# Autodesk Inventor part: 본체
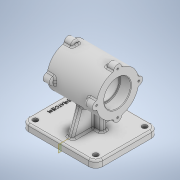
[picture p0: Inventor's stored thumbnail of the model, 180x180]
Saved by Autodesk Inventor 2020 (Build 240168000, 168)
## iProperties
Created: 2022-11
Part Number: 본체
Material: 일반
Document SubType Name: Modeling
Designer: owner
Density: 1 g/cm^3
Appearance: 기본값
Mass: 450.145 g
Surface Area: 796.917 cm^2
Volume: 450.145 cm^3
Author: owner
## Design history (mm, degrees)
sketch "스케치1"
  geometry: L1 (65, 55)-(-65, 55); L2 (-65, 55)-(-65, -55); L3 (-65, -55)-(65, -55); L4 (65, -55)-(65, 55); L5 (65, 55)-(-65, -55); L6 (-65, 55)-(65, -55); 1 further point
  constraints: 12 end point, 2 midpoint, 2 parallel, 1 horizontal, 1 perpendicular
  dimensions: "d0" = 130 distance of L3.end L2.end; "d1" = 110 distance of L2.end L1.end
extrude "돌출1" new body sketch "스케치1" distance "d2" = 12; taper "d3" = 0 deg
node "작업 평면1"
sketch "스케치2"
  geometry: L1 (0, 0)-(110, 0) reference; C1 r 37 at (55, 82); 2 further points
  constraints: 1 centre point, 1 midpoint, 1 vertical alignment
  dimensions: "d5" = 74 diameter of C1; "d6" = 82 distance from line of L1 C1.centre
extrude "돌출2" join sketch "스케치2" stored distance "d7" = 87; taper "d8" = 0 deg
sketch "스케치3"
  geometry: C1 r 37 at (0, 0) reference; 2 further points
  constraints: 1 coincident
hole "구멍1" sketch "스케치3" at (0, 0) diameter "d9" = 42; stored, may be unused: countersink angle "d13" = 90 deg, drill point angle "d15" = 0 deg; dims "d10" = 8, "d11" = 47, "d12" = 19, "d14" = 10
sketch "스케치4"
  geometry: C1 r 37 at (0, 0) reference; 2 further points
  constraints: 1 coincident
hole "구멍2" sketch "스케치4" at (0, 0) diameter "d16" = 42; stored, may be unused: countersink angle "d20" = 90 deg, drill point angle "d22" = 0 deg; dims "d17" = 8, "d18" = 47, "d19" = 19, "d21" = 10
sketch "스케치5"
  geometry: L1 (110, 0)-(0, 0) reference; L2 (0, 0)-(0, 12) reference; L3 (110, 12)-(0, 12) reference; L4 (110, 0)-(110, 12) reference; L5 (110, 12)-(0, 12) reference; L6 (96, 12)-(80.336, 55.036); L7 (14, 12)-(29.664, 55.036); C1 r 23.5 at (55, 82) reference; A1 r 37 centre (55, 82) between (80.336, 55.036) and (29.664, 55.036) reference; 3 further points
  constraints: 4 end point, 2 point on circle, 2 point on line
  dimensions: "d23" = 14 distance from line of L4 L6.start; "d24" = 14 distance from line of L2 L7.start; "d25" = 110 deg angle of L3 L6; "d26" = 110 deg angle of L3 L7
extrude "돌출3" join sketch "스케치5" stored distance "d27" = 10; taper "d28" = 0 deg
sketch "스케치6"
  geometry: L1 (-65, 12)-(65, 12) reference; L2 (-15, 12)-(-15, 30.85); L3 (5, -23.8)-(5, 142.8) reference; 1 further point
  constraints: 2 end point, 1 point on line, 1 vertical
  dimensions: "d29" = 20 distance between parallel lines of L3 L2
feature "리브1" sketch "스케치6" dims "d30" = 1, "d31" = 10, "d32" = 0, "d33" = 0, "d34" = 1, "d35" = 1
sketch "스케치7"
  geometry: C1 r 7 at (0, 37); 4 further points
  constraints: 1 centre point, 2 other
  dimensions: "d36" = 14 diameter of C1
extrude "돌출4" join sketch "스케치7" distance "d37" = 14; taper "d38" = 0 deg
sketch "스케치8"
  geometry: A1 r 7 centre (-55, 119) between (-48.031, 118.338) and (-61.969, 118.338) reference; 2 further points
  constraints: 1 coincident
hole "구멍3" sketch "스케치8" at (-55, 119) diameter "d39" = 3.242; stored, may be unused: countersink angle "d43" = 90 deg, drill point angle "d45" = 118 deg; dims "d40" = 8, "d41" = 47, "d42" = 19, "d44" = 10
fillet "모깎기1" dims "d46" = 3
fillet "모깎기2" dims "d47" = 3
fillet "모깎기3" dims "d51" = 12
sketch "스케치9"
  geometry: A1 r 12 centre (-53, -43) between (-65, -43) and (-53, -55) reference; A2 r 12 centre (-53, 43) between (-53, 55) and (-65, 43) reference; A3 r 12 centre (53, -43) between (53, -55) and (65, -43) reference; A4 r 12 centre (53, 43) between (65, 43) and (53, 55) reference; 5 further points
  constraints: 4 coincident
hole "구멍4" sketch "스케치9" at (-53, -43), (-53, 43), (53, -43), (53, 43) diameter "d52" = 9; stored, may be unused: countersink angle "d56" = 90 deg, drill point angle "d58" = 0 deg; dims "d53" = 8, "d54" = 47, "d55" = 19, "d57" = 10
fillet "모깎기4" dims "d59" = 3
fillet "모깎기5" dims "d60" = 3
fillet "모깎기6" dims "d61" = 3
fillet "모깎기7" dims "d62" = 3
fillet "모깎기8" dims "d63" = 1
chamfer "모따기1" distance "d64" = 1; stored, may be unused: second distance "d65" = 2, angle "d66" = 45 deg
sketch "스케치10"
  geometry: L1 (5, -77)-(5, 77) reference; 2 further points
  constraints: 1 horizontal alignment, 1 other
  dimensions: "d67" = 58 distance from line of point (-53, 0) L1
feature "엠보싱1" sketch "스케치10" dims "d0" = 130, "d1" = 110, "d68" = 0.5, "d69" = 0
node "솔리드1"
mirror "미러1"
pattern_circular "원형 패턴1" dims "d49" = 360 deg
mirror "미러2"
node "투영된 루프1"
node "투영된 루프2"
feature "A9D066F2-1C7D-4E18-AEED-F7BC21143FA4" dims "d9" = 42, "d10" = 8, "d11" = 47, "d12" = 19, "d13" = 90 deg, "d14" = 10, "d15" = 0
